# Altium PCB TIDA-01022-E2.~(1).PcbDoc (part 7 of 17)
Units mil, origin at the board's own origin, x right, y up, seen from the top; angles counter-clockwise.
Board outline 6929.13 x 11614.17 mil, 12 copper layers (L1_Top Layer, L2_GND, L3_GND, L4_Signal Layer 1, L5_GND, L6_PWR, L7_GND/PWR, L8_PWR, L9_GND/PWR, L10_Signal Layer 2, L11_GND, L12_Bottom Layer), stack 64.6 mil thick; 1711 components, 1001 nets, 5985 pads, 3200 vias.
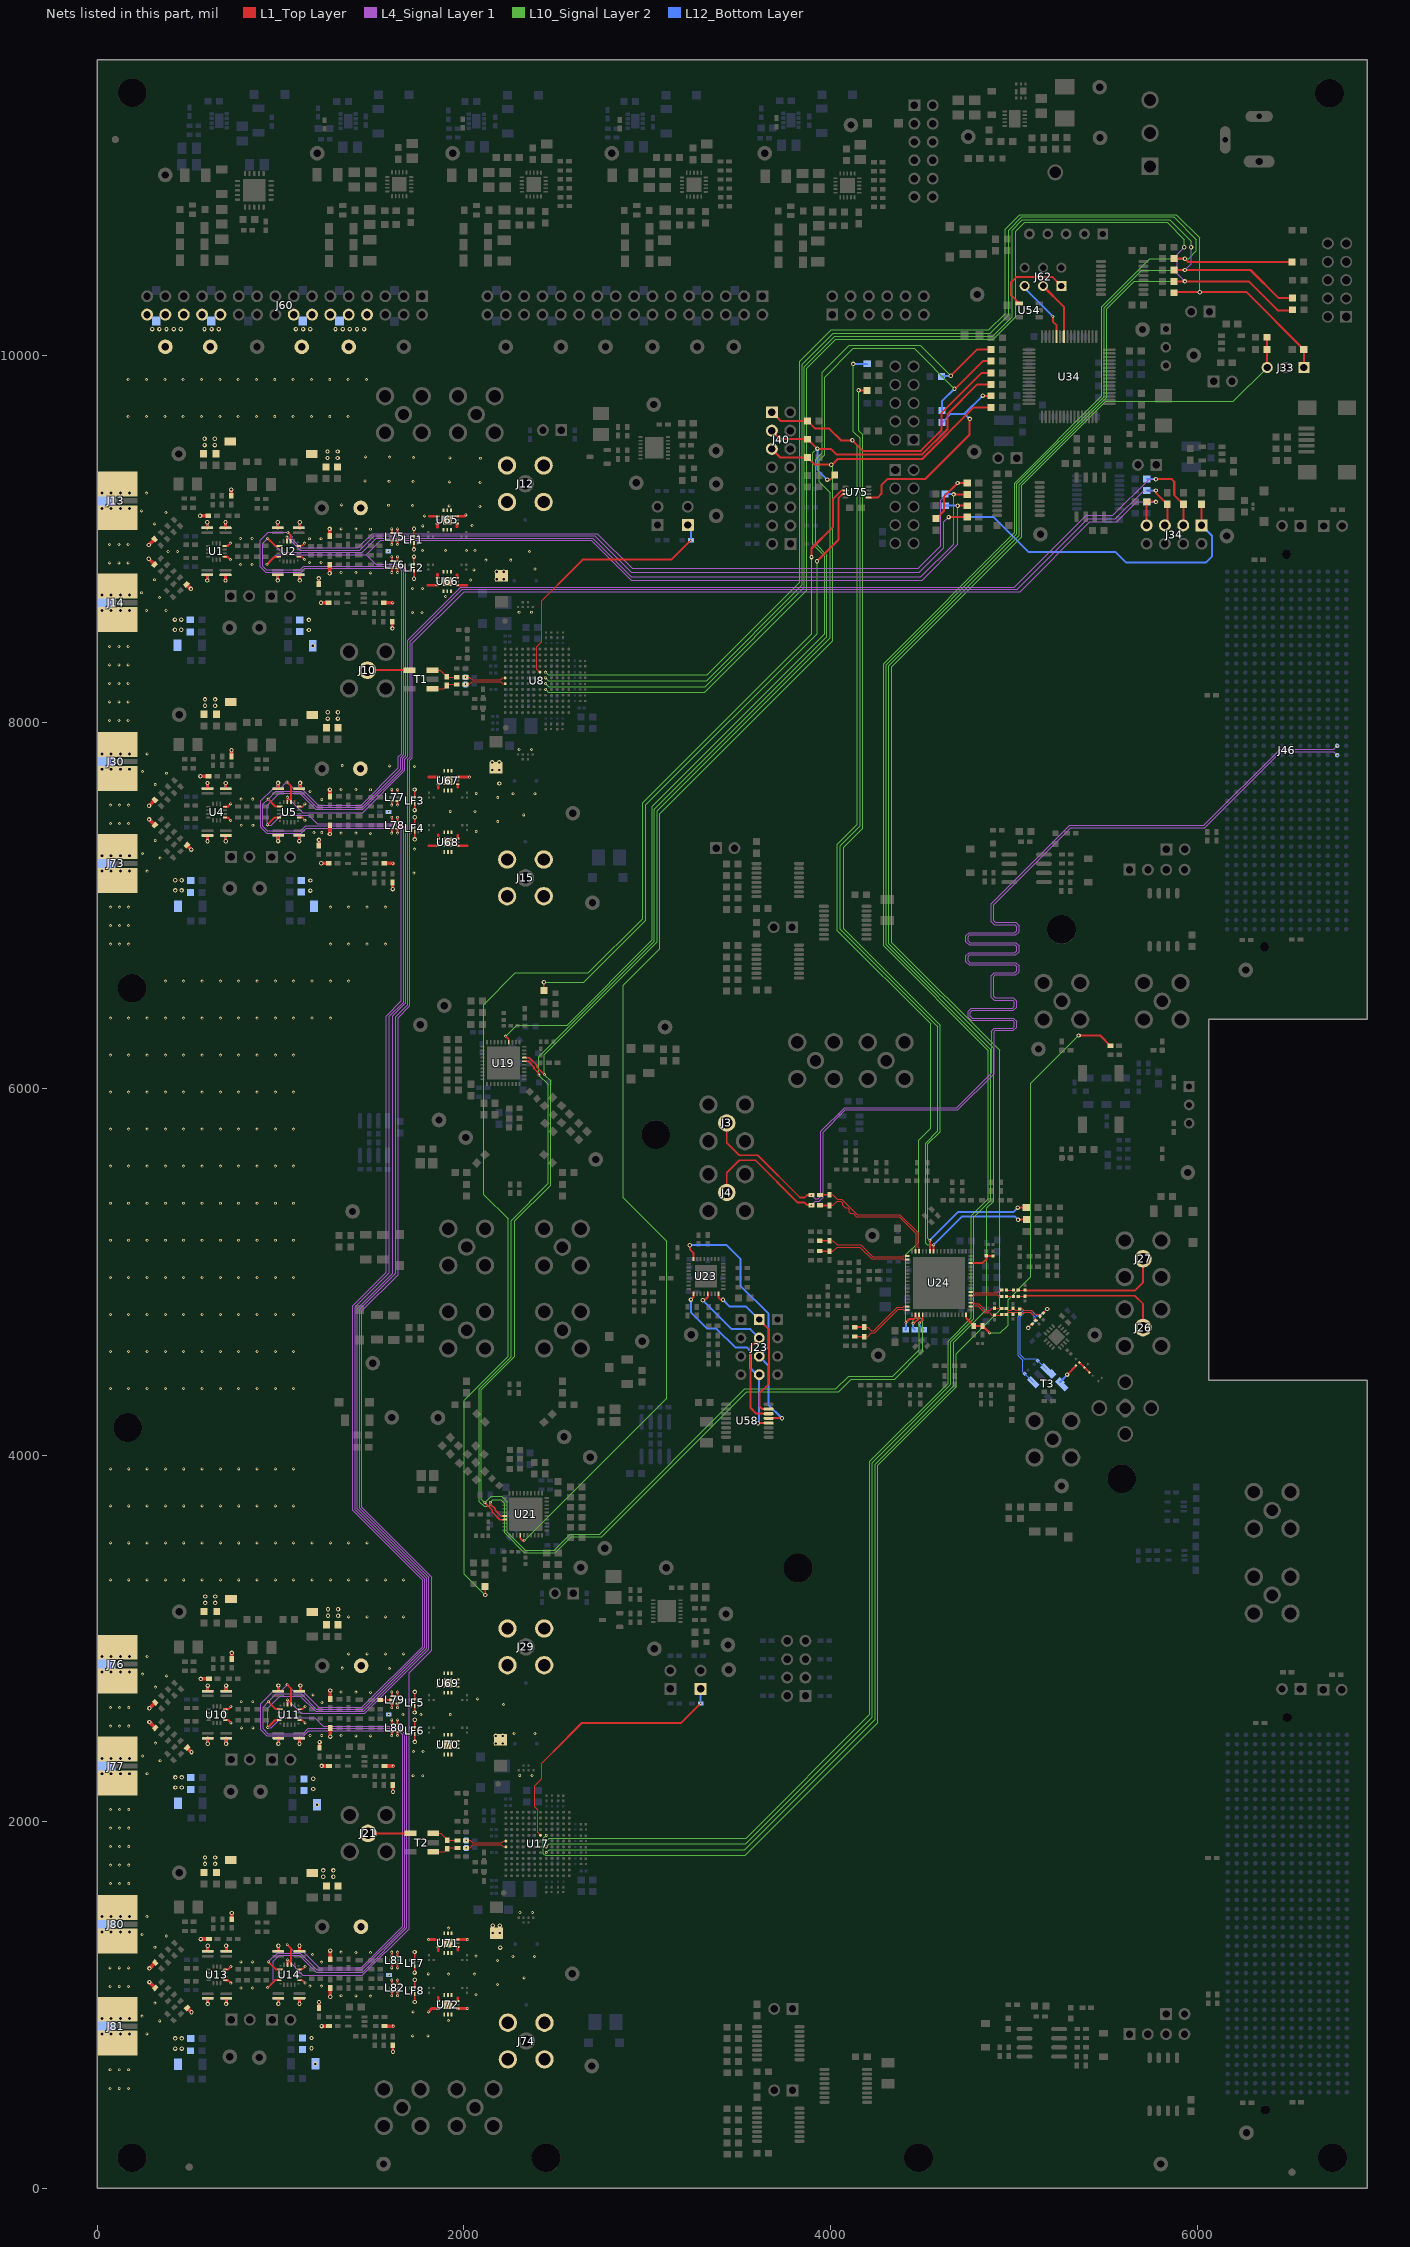
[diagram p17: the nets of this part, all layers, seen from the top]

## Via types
v1: diameter 16, hole 8, L1_Top Layer to L12_Bottom Layer, tented both sides, 1699 vias
v2: diameter 24, hole 12, L1_Top Layer to L12_Bottom Layer, tented both sides, 1501 vias

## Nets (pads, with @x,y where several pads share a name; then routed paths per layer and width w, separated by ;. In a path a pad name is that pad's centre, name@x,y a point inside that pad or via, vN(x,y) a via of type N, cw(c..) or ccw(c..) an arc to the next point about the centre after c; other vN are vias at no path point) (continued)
AGND: C1.2 C2.1 C3.1 C4.1 C5.1 C6.2 C7.2 C8.2 C9.2 C10.2 C12.2 C15.2 C17.2 C18.2 C19.2 C20.2 C21.1 C22.1 C23.1 C24.1 C25.1 C27.2 C28.2 C35.2 C36.1 C37.1 C38.1 C39.1 C40.2 C41.2 C42.2 C43.2 C44.2 C46.2 C49.2 C51.2 C52.2 C53.2 C54.2 C55.1 C56.1 C57.1 C58.1 C59.1 C61.2 C62.2 C161.2 C162.1 C163.1 C164.1 C165.1 C166.2 C167.2 C168.2 C169.2 C170.2 C172.2 C175.2 C177.2 C178.2 C179.2 C180.2 C181.1 C182.1 C183.1 C184.1 C185.1 C187.2 C188.2 C195.2 C196.1 C197.1 C198.1 C199.1 C200.2 C201.2 C202.2 C203.2 C204.2 C206.2 C209.2 C211.2 C212.2 C213.2 C214.2 C215.1 C216.1 C217.1 C218.1 C219.1 C221.2 C222.2 C637.2 C638.2 C639.1 C640.2 C641.1 C642.2 C648.2 C649.1 C650.2 C651.1 C652.2 C653.2 C658.2 C659.2 C663.1 C664.2 C665.1 C666.2 C670.2 C671.2 C672.1 C673.2 C674.1 C675.2 C688.2 C689.2 C691.1 C692.2 C693.1 C694.2 C699.2 C700.2 C701.1 C702.2 C703.1 C704.2 C708.2 C709.2 C710.1 C711.2 C712.1 C713.2 C717.2 C718.2 C719.1 C720.2 C721.1 C722.2 J12.2 J12.3 J12.4 J12.5 J13. J13.2 J13.3 J13.4 J14. J14.2 J14.3 J14.4 J15.2 J15.3 J15.4 J15.5 J29.2 J29.3 J29.4 J29.5 J30. J30.2 J30.3 J30.4 J60.8 J60.10 J60.12 J60.14 J60.16 J60.24 J60.26 J60.28 J60.30 J60.32 J73. J73.2 J73.3 J73.4 J74.2 J74.3 J74.4 J74.5 J76. J76.2 J76.3 J76.4 J77. J77.2 J77.3 J77.4 J80. J80.2 J80.3 J80.4 J81. J81.2 J81.3 J81.4 L68.2 L69.2 L70.2 L71.2 L75.1 L75.3 L75.4 L75.6 L76.1 L76.3 L76.4 L76.6 L77.1 L77.3 L77.4 L77.6 L78.1 L78.3 L78.4 L78.6 L79.1 L79.2 L79.3 L79.4 L79.6 L80.1 L80.3 L80.4 L80.6 L81.1 L81.3 L81.4 L81.6 L82.1 L82.3 L82.4 L82.6 L93.1 L94.1 L95.1 L96.1 LF1.2 LF1.5 LF2.2 LF2.5 LF3.2 LF3.5 LF4.2 LF4.5 LF5.2 LF5.5 LF6.2 LF6.5 LF7.2 LF7.5 LF8.2 LF8.5 R20.1 R21.1 R44.1 R45.1 R85.2 R101.1 R102.1 R125.1 R126.1 R483.1 R555.1 R558.1 R559.1 R564.1 R567.1 R568.1 R573.1 R576.1 R577.1 R582.1 R585.1 R642.1 TP15.1 TP28.1 TP29.1 TP50.1 TP51.1 TP52.1 TP53.1 TP64.1 U1.11 U1.14 U2.9 U2.12 U4.11 U4.14 U5.9 U5.12 U10.11 U10.14 U11.9 U11.12 U13.11 U13.14 U14.9 U14.12 U65.1 U65.3 U65.4 U65.5 U65.6 U65.7 U65.9 U65.10 U65.11 U65.12 U65.13 U66.1 U66.3 U66.4 U66.5 U66.6 U66.7 U66.9 U66.10 U66.11 U66.12 U66.13 U67.1 U67.3 U67.4 U67.5 U67.6 U67.7 U67.9 U67.10 U67.11 U67.12 U67.13 U68.1 U68.3 U68.4 U68.5 U68.6 U68.7 U68.9 U68.10 U68.11 U68.12 U68.13 U69.1 U69.3 U69.4 U69.5 U69.6 U69.7 U69.9 U69.10 U69.11 U69.12 U69.13 U70.1 U70.3 U70.4 U70.5 U70.6 U70.7 U70.9 U70.10 U70.11 U70.12 U70.13 U71.1 U71.3 U71.4 U71.5 U71.6 U71.7 U71.9 U71.10 U71.11 U71.12 U71.13 U72.1 U72.3 U72.4 U72.5 U72.6 U72.7 U72.9 U72.10 U72.11 U72.12 U72.13 | length 6689.4
  L1_Top Layer w8: U2.9@1099.21,8901.73 1114.81,8901.73 v1(1130.22,8886.32) ; U2.12@1099.21,8960.79 1114.81,8960.79 v1(1130.22,8976.2) ; U5.9@1101.01,7479.6 1116.6,7479.6 v1(1132.02,7464.19) ; U5.12@1101.01,7538.66 1116.6,7538.66 v1(1132.02,7554.07) ; U11.9@1102.53,2555.37 1118.12,2555.37 v1(1133.53,2539.96) ; U11.12@1102.53,2614.42 1118.12,2614.42 v1(1133.53,2629.84) ; U14.9@1102.6,1136.03 1118.2,1136.03 v1(1133.61,1120.62) ; U14.12@1102.6,1195.09 1118.2,1195.09 v1(1133.61,1210.5) ; v2(1727.01,8941.88) 1727.01,8977.01 LF1.5@1727.22,8977.22 ; LF1.2@1727.13,9010.68 v2(1727.13,9054.33) ; LF2.2@1727.22,8859 v2(1727.22,8902.65) ; v2(1727.41,8781.89) LF2.5@1727.41,8825.54 ; v2(1730.63,1177.1) 1730.63,1212.23 LF7.5@1730.84,1212.44 ; v2(1730.63,2596.2) 1730.63,2631.33 LF5.5@1730.84,2631.54 ; v2(1730.63,7519.8) 1730.63,7554.93 LF3.5@1730.84,7555.14 ; LF7.2@1730.74,1245.9 v2(1730.74,1289.55) ; LF3.2@1730.74,7588.6 v2(1730.74,7632.25) ; LF8.2@1730.84,1093.9 v2(1730.84,1137.87) ; LF6.2@1730.84,2513 v2(1730.84,2556.97) ; LF5.2@1730.84,2665 v2(1730.84,2708.65) ; LF4.2@1730.84,7436.6 v2(1730.84,7480.57) ; v2(1731.03,1017.11) LF8.5@1731.03,1060.75 ; v2(1731.03,7359.81) LF4.5@1731.03,7403.45 ; v2(1731.12,2436.21) LF6.5@1731.12,2479.85
  L1_Top Layer w10: v1(1606,7546.6) L77.3@1606,7569.91 ; v1(1637.5,7546.6) L77.4@1637.5,7569.91
  L1_Top Layer w11: R85.2@1542.66,2664.77 cw(c1543.97,2663.46) 1543.97,2665.31 R642.1@1598.13,2665.31 ; v1(1606,1050.9) L82.3@1606,1074.21 ; L82.1@1606,1113.59 v1(1606,1136.9) ; v1(1606,1202.9) L81.3@1606,1226.22 ; L81.1@1606,1265.59 v1(1606,1288.9) ; v1(1606,2470.31) L80.3@1606,2493.31 L80.3@1606,2493.63 ; L80.1@1606,2533 v1(1606,2556.31) ; v1(1606,2622.31) L79.3@1606,2645.63 ; L79.1@1606,2685 v1(1606,2708.31) ; v1(1606,7394.6) L78.3@1606,7417.71 L78.3@1606,7417.91 ; L78.1@1606,7457.28 v1(1606,7480.6) ; L77.1@1606,7609.28 v1(1606,7632.6) ; v1(1606,8816) L76.3@1606,8839.31 ; L76.1@1606,8878.69 v1(1606,8902) ; v1(1606,8968) L75.3@1606,8991.31 ; L75.1@1606,9030.69 v1(1606,9054) ; v1(1637.5,1050.9) L82.4@1637.5,1074.21 ; L82.6@1637.5,1113.59 v1(1637.5,1136.9) ; v1(1637.5,1202.9) L81.4@1637.5,1226.22 ; L81.6@1637.5,1265.59 v1(1637.5,1288.9) ; v1(1637.5,2470.31) L80.4@1637.5,2493.31 L80.4@1637.5,2493.63 ; L80.6@1637.5,2533 v1(1637.5,2556.31) ; v1(1637.5,2622.31) L79.4@1637.5,2645.63 ; L79.6@1637.5,2685 v1(1637.5,2708.31) ; v1(1637.5,7394.6) L78.4@1637.5,7417.71 L78.4@1637.5,7417.91 ; L78.6@1637.5,7457.28 v1(1637.5,7480.6) ; L77.6@1637.5,7609.28 v1(1637.5,7632.6) ; v1(1637.5,8816) L76.4@1637.5,8839.31 ; L76.6@1637.5,8878.69 v1(1637.5,8902) ; v1(1637.5,8968) L75.4@1637.5,8991.31 ; L75.6@1637.5,9030.69 v1(1637.5,9054)
  L1_Top Layer w12: U1.11@694.19,8901.46 709.78,8901.46 v1(725.19,8886.05) ; U1.14@694.19,8960.52 709.78,8960.52 v1(725.19,8975.93) ; U4.11@695.98,7479.34 711.58,7479.34 v1(726.99,7463.92) ; U4.14@695.98,7538.39 711.58,7538.39 v1(726.99,7553.8) ; U10.11@697.5,2555.1 713.1,2555.1 v1(728.51,2539.69) ; U10.14@697.5,2614.16 713.1,2614.16 v1(728.51,2629.57) ; U13.11@697.58,1135.76 713.17,1135.76 v1(728.59,1120.35) ; U13.14@697.58,1194.82 713.17,1194.82 v1(728.59,1210.23)
  L1_Top Layer w15: v2(598.91,8772.33) C21.1@598.91,8803.19 ; C2.1@598.91,9058.79 v2(598.91,9089.65) ; v2(600.71,7350.21) C55.1@600.71,7381.07 ; C36.1@600.71,7636.66 v2(600.71,7667.52) ; v2(602.23,2425.97) C181.1@602.23,2456.83 ; C162.1@602.23,2712.42 v2(602.23,2743.29) ; v2(602.3,1006.64) C215.1@602.3,1037.5 ; C196.1@602.3,1293.09 v2(602.3,1323.95) ; v2(698.91,8772.33) C22.1@698.91,8803.19 ; C3.1@698.91,9058.79 v2(698.91,9089.65) ; v2(700.71,7350.21) C56.1@700.71,7381.07 ; C37.1@700.71,7636.66 v2(700.71,7667.52) ; v2(702.23,2425.97) C182.1@702.23,2456.83 ; C163.1@702.23,2712.42 v2(702.23,2743.29) ; v2(702.3,1006.64) C216.1@702.3,1037.5 ; C197.1@702.3,1293.09 v2(702.3,1323.95) ; v2(984.09,8772.6) C23.1@984.09,8803.46 ; C4.1@984.09,9059.05 v2(984.09,9089.92) ; v2(985.89,7350.47) C57.1@985.89,7381.34 ; C38.1@985.89,7636.93 v2(985.89,7667.79) ; v2(987.41,2426.24) C183.1@987.41,2457.1 ; C164.1@987.41,2712.69 v2(987.41,2743.55) ; v2(987.48,1006.9) C217.1@987.48,1037.77 ; C198.1@987.48,1293.36 v2(987.48,1324.22) ; v2(1100.89,7350.47) C58.1@1100.89,7381.34 ; v2(1102.41,2426.24) C184.1@1102.41,2457.1 ; v2(1102.48,1006.9) C218.1@1102.48,1037.76 ; C199.1@1102.48,1293.36 v2(1102.48,1324.22) ; v2(1104.09,8772.6) C24.1@1104.09,8803.46 ; C5.1@1104.09,9059.05 v2(1104.09,9089.92) ; C39.1@1105.89,7636.93 v2(1105.89,7667.79) ; C165.1@1107.41,2712.69 v2(1107.41,2743.55) ; C27.2@1207.68,8752.9 v2(1207.68,8783.76) ; C61.2@1208.47,7326.37 v2(1208.47,7357.24) ; C221.2@1209.11,984.88 v2(1209.11,1015.74) ; C187.2@1212.04,2404.21 v2(1212.04,2435.08) ; R558.1@1607.91,8547.16 1607.91,8512.21 v2(1609.19,8510.93) ; R567.1@1609.71,7125.04 1609.71,7090.09 v2(1610.99,7088.8) ; R576.1@1611.23,2200.8 1611.23,2165.85 v2(1612.51,2164.57) ; R585.1@1611.3,781.47 1611.3,746.52 v2(1612.59,745.23) ; 1803.55,8746.76 U66.3@1855.38,8746.76 ; v1(1805.24,963.3) 1823.92,981.98 U72.3@1859,981.98 ; v1(1807.16,1357.84) U71.1@1859,1357.84 ; 1807.16,7324.68 U68.3@1859,7324.68 ; 1807.16,7700.54 U67.1@1859,7700.54 ; 1810,9122.62 U65.1@1855.38,9122.62 ; U66.1@1855.38,8786.92 1855.38,8806.6 ; 1855.38,9062.78 U65.3@1855.38,9082.46 ; U72.1@1859,1022.14 1859,1041.81 ; 1859,1298 U71.3@1859,1317.68 ; U68.1@1859,7364.84 1859,7384.52 ; 1859,7640.7 U67.3@1859,7660.38 ; U66.7@1962.46,8746.76 2014.3,8746.76 ; U66.9@1962.46,8786.92 1962.46,8803.52 ; 1962.46,9065.86 U65.7@1962.46,9082.46 ; U65.9@1962.46,9122.62 2002.62,9122.62 v1(2010,9130) ; U72.7@1966.08,981.98 v1(2017.91,981.98) ; U72.9@1966.08,1022.14 1966.08,1038.74 ; 1966.08,1301.08 U71.7@1966.08,1317.68 ; U71.9@1966.08,1357.84 v1(2017.91,1357.84) ; U68.7@1966.08,7324.68 2017.91,7324.68 ; U68.9@1966.08,7364.84 1966.08,7381.44 ; 1966.08,7643.78 U67.7@1966.08,7660.38 ; U67.9@1966.08,7700.54 1966.62,7700 v1(2030,7700)
  L1_Top Layer w20: v2(280.45,8891.05) R21.1@312.21,8859.29 ; v2(280.45,8965.93) R20.1@312.21,8997.69 ; v2(282.24,7468.92) R45.1@314.01,7437.16 ; v2(282.24,7543.8) R44.1@314.01,7575.57 ; v2(283.76,2544.69) R102.1@315.52,2512.93 ; v2(283.76,2619.57) R101.1@315.52,2651.33 ; v2(283.84,1125.35) R126.1@315.6,1093.59 ; v2(283.84,1200.23) R125.1@315.6,1232 ; R555.1@485.91,8750.79 v2(510.19,8726.5) ; R564.1@487.71,7328.66 v2(511.99,7304.37) ; R573.1@489.23,2404.42 v2(513.51,2380.14) ; R582.1@489.3,985.09 v2(513.59,960.8) ; v2(560.31,9125.93) 560.25,9125.99 C1.2@604.79,9125.99 ; v2(562.11,7703.8) 562.05,7703.86 C35.2@606.59,7703.86 ; v2(563.63,2779.57) 563.57,2779.63 C161.2@608.11,2779.63 ; v2(563.7,1360.23) 563.65,1360.29 C195.2@608.18,1360.29 ; R483.1@729.91,9234.41 v2(729.91,9268.12) ; R559.1@731.71,7812.28 v2(731.71,7846) ; R568.1@733.23,2888.05 v2(733.23,2921.76) ; R577.1@733.3,1468.71 v2(733.3,1502.43) ; v2(1219.87,8651.26) C25.1@1260.47,8651.26 ; v2(1221.67,7229.13) C59.1@1262.27,7229.13 ; v2(1223.18,2304.9) C185.1@1263.79,2304.9 ; v2(1223.26,885.56) C219.1@1263.86,885.56 ; C15.2@1266.72,8858.51 1266.87,8858.36 v2(1266.87,8811.43) ; C10.2@1266.72,9015.76 v2(1266.72,9053.6) ; C44.2@1268.52,7593.63 v2(1268.52,7631.48) ; v2(1268.67,7389.3) C49.2@1268.67,7436.24 ; C170.2@1269.89,2669.54 v2(1269.89,2716.48) ; C204.2@1269.96,1250.21 v2(1269.96,1297.14) ; C175.2@1270.04,2512.15 1270.19,2512 v2(1270.19,2465.07) ; v2(1270.26,1045.73) C209.2@1270.26,1092.67 ; C28.2@1562.71,8651.26 1610.52,8651.26 v1(1610.52,8650.6) ; C62.2@1564.51,7229.13 1612.32,7229.13 v1(1612.32,7228.48) ; C188.2@1566.03,2304.9 1613.84,2304.9 v1(1613.84,2304.24) ; C222.2@1566.11,885.56 v1@1613.91,885.56
  L12_Bottom Layer w15: v2(598.91,8772.33) C17.2@598.91,8803.19 ; C6.2@598.91,9058.79 v2(598.91,9089.65) ; v2(600.71,7350.21) C51.2@600.71,7381.07 ; C40.2@600.71,7636.66 v2(600.71,7667.52) ; v2(602.23,2425.97) C177.2@602.23,2456.83 ; C166.2@602.23,2712.42 v2(602.23,2743.29) ; v2(602.3,1006.64) C211.2@602.3,1037.5 ; C200.2@602.3,1293.09 v2(602.3,1323.95) ; v2(698.91,8772.33) C18.2@698.91,8803.19 ; C7.2@698.91,9058.79 v2(698.91,9089.65) ; v2(700.71,7350.21) C52.2@700.71,7381.07 ; C41.2@700.71,7636.66 v2(700.71,7667.52) ; v2(702.23,2425.97) C178.2@702.23,2456.83 ; C167.2@702.23,2712.42 v2(702.23,2743.29) ; v2(702.3,1006.64) C212.2@702.3,1037.5 ; C201.2@702.3,1293.09 v2(702.3,1323.95) ; v2(984.09,8772.6) C19.2@984.09,8803.46 ; C8.2@984.09,9059.05 v2(984.09,9089.92) ; v2(985.89,7350.47) C53.2@985.89,7381.34 ; C42.2@985.89,7636.93 v2(985.89,7667.79) ; v2(987.41,2426.24) C179.2@987.41,2457.1 ; C168.2@987.41,2712.69 v2(987.41,2743.55) ; v2(987.48,1006.9) C213.2@987.48,1037.77 ; C202.2@987.48,1293.36 v2(987.48,1324.22) ; v2(1100.89,7350.47) C54.2@1100.89,7381.34 ; v2(1102.41,2426.24) C180.2@1102.41,2457.1 ; v2(1102.48,1006.9) C214.2@1102.48,1037.77 ; C203.2@1102.48,1293.36 v2(1102.48,1324.22) ; v2(1104.09,8772.6) C20.2@1104.09,8803.46 ; C9.2@1104.09,9059.05 v2(1104.09,9089.92) ; C43.2@1105.89,7636.93 v2(1105.89,7667.79) ; C169.2@1107.41,2712.69 v2(1107.41,2743.55)
  other v1: 69.24,546.21 119.24,546.21 169.24,546.21 69.24,647.21 119.24,647.21 169.24,647.21 1720.14,832.11 1803.14,832.11 269.51,843 1613.91,884.91 340.23,913.71 1915,915 243.4,939.82 1722.24,963.3 1912.54,1002.06 314.11,1010.53 1490.13,1048.9 1410,1049.9 1329.87,1050.9 2065.45,1058.43 783.24,1093.3 846.24,1093.3 69.24,1102.3 119.24,1102.3 169.24,1102.3 1159.24,1103.3 1222.24,1103.3 2182.45,1113.43 2328,1148 1591.36,1163.94 1805,1170 1915,1169.43 2058.45,1169.43 69.24,1203.3 119.24,1203.3 169.24,1203.3 1222.24,1234.3 782.77,1235.7 845.77,1235.7 2182.45,1244.43 2266.45,1265.43 2385.45,1265.43 2065.45,1267.43 1174,1276 1489.98,1286.9 1409.85,1287.9 1329.72,1288.9 314.11,1315.55 1912.54,1337.76 375.58,1377.02 243.4,1386.27 1915,1420 269.51,1483.09 2305.26,1505.23 2372.85,1505.23 71.08,1662.55 121.08,1662.55 171.08,1662.55 71.08,1763.55 121.08,1763.55 171.08,1763.55 71.08,1864.55 121.08,1864.55 171.08,1864.55 71.08,1965.55 121.08,1965.55 171.08,1965.55 71.08,2066.55 121.08,2066.55 171.08,2066.55 1721.98,2251.45 1774.98,2251.45 2304.05,2253.38 2371.64,2253.38 271.36,2262.33 342.07,2333.04 245.24,2359.15 1724.08,2382.64 1777.08,2382.64 315.95,2429.86 1490.13,2468.31 1410,2469.31 1161,2471 1224,2471 1329.87,2470.31 2273,2482 2387,2482 785.08,2512.64 848.08,2512.64 71.08,2521.64 121.08,2521.64 171.08,2521.64 1667,2585 1765,2585 1925,2585 1589.76,2585.46 71.08,2622.64 121.08,2622.64 171.08,2622.64 2216,2639 1225.04,2651.97 784.61,2655.03 847.61,2655.03 2074,2671 1177,2693 1489.98,2706.31 1409.85,2707.31 1329.72,2708.31 315.95,2734.89 1912.54,2756.86 377.42,2796.36 245.24,2805.6 1593.09,2836.33 1335.9,2838.43 271.36,2902.42 1371,2916 1471,2916 1571,2916 1671,2916 1371,3118 1471,3118 1571,3118 1671,3118 71,3320 171,3320 271,3320 371,3320 471,3320 571,3320 671,3320 771,3320 871,3320 971,3320 1071,3320 1171,3320 1271,3320 1371,3320 1471,3320 1571,3320 1671,3320 71,3522 171,3522 271,3522 371,3522 471,3522 571,3522 671,3522 771,3522 871,3522 971,3522 1071,3522 1171,3522 1271,3522 1371,3522 1471,3522 71,3724 171,3724 271,3724 371,3724 471,3724 571,3724 671,3724 771,3724 871,3724 971,3724 1071,3724 71,3926 171,3926 271,3926 371,3926 471,3926 571,3926 671,3926 771,3926 871,3926 971,3926 1071,3926 70.8,4364.78 170.8,4364.78 270.8,4364.78 370.8,4364.78 470.8,4364.78 570.8,4364.78 670.8,4364.78 770.8,4364.78 870.8,4364.78 970.8,4364.78 1070.8,4364.78 70.8,4566.78 170.8,4566.78 270.8,4566.78 370.8,4566.78 470.8,4566.78 570.8,4566.78 670.8,4566.78 770.8,4566.78 870.8,4566.78 970.8,4566.78 1070.8,4566.78 70.8,4768.78 170.8,4768.78 270.8,4768.78 370.8,4768.78 470.8,4768.78 570.8,4768.78 670.8,4768.78 770.8,4768.78 870.8,4768.78 970.8,4768.78 1070.8,4768.78 70.8,4970.78 170.8,4970.78 270.8,4970.78 370.8,4970.78 470.8,4970.78 570.8,4970.78 670.8,4970.78 770.8,4970.78 870.8,4970.78 970.8,4970.78 1070.8,4970.78 70.8,5172.78 170.8,5172.78 270.8,5172.78 370.8,5172.78 470.8,5172.78 570.8,5172.78 670.8,5172.78 770.8,5172.78 870.8,5172.78 970.8,5172.78 1070.8,5172.78 70.8,5374.78 170.8,5374.78 270.8,5374.78 370.8,5374.78 470.8,5374.78 570.8,5374.78 670.8,5374.78 770.8,5374.78 870.8,5374.78 970.8,5374.78 1070.8,5374.78 70.8,5576.78 170.8,5576.78 270.8,5576.78 370.8,5576.78 470.8,5576.78 570.8,5576.78 670.8,5576.78 770.8,5576.78 870.8,5576.78 970.8,5576.78 1070.8,5576.78 70.8,5778.78 170.8,5778.78 270.8,5778.78 370.8,5778.78 470.8,5778.78 570.8,5778.78 670.8,5778.78 770.8,5778.78 870.8,5778.78 970.8,5778.78 1070.8,5778.78 70.8,5980.78 170.8,5980.78 270.8,5980.78 370.8,5980.78 470.8,5980.78 570.8,5980.78 670.8,5980.78 770.8,5980.78 870.8,5980.78 970.8,5980.78 1070.8,5980.78 70.8,6182.78 170.8,6182.78 270.8,6182.78 370.8,6182.78 470.8,6182.78 570.8,6182.78 670.8,6182.78 770.8,6182.78 870.8,6182.78 970.8,6182.78 1070.8,6182.78 70.8,6384.78 170.8,6384.78 270.8,6384.78 370.8,6384.78 470.8,6384.78 570.8,6384.78 670.8,6384.78 770.8,6384.78 870.8,6384.78 970.8,6384.78 1070.8,6384.78 1170.8,6384.78 1270.8,6384.78 370.8,6586.78 470.8,6586.78 570.8,6586.78 670.8,6586.78 770.8,6586.78 870.8,6586.78 970.8,6586.78 1070.8,6586.78 1170.8,6586.78 1270.8,6586.78 1370.8,6586.78 70.8,6788.78 120.8,6788.78 170.8,6788.78 1270.8,6788.78 1370.8,6788.78 1470.8,6788.78 1570.8,6788.78 70.8,6889.78 120.8,6889.78 170.8,6889.78 70.8,6990.78 120.8,6990.78 170.8,6990.78 1270.8,6990.78 1370.8,6990.78 1470.8,6990.78 1570.8,6990.78 1727,7176 271.07,7186.57 341.78,7257.28 244.96,7283.39 1729.1,7307.19 1925,7344.31 315.67,7354.1 1490.13,7392.6 1410,7393.6 1329.87,7394.6 1181,7397 1224,7397 2067,7402 784.8,7436.87 847.8,7436.87 70.8,7445.87 120.8,7445.87 170.8,7445.87 2184,7457 2326,7494 1588.24,7509.7 1925,7513 2060,7513 70.8,7546.87 120.8,7546.87 170.8,7546.87 1223.8,7577.87 784.33,7579.27 847.33,7579.27 2184,7588 2268,7609 2387,7609 2067,7611 1161,7622 1489.98,7630.6 1409.85,7631.6 1329.72,7632.6 315.67,7659.13 1925,7680 377.14,7720.59 244.96,7729.84 1731,7758 1592.81,7760.57 1335.62,7762.66 271.07,7826.66 2301.08,7851.2 2368.67,7851.2 67,8008.91 117,8008.91 167,8008.91 67,8109.91 117,8109.91 167,8109.91 67,8210.91 117,8210.91 167,8210.91 67,8311.91 117,8311.91 167,8311.91 67,8412.91 117,8412.91 167,8412.91 1717.9,8597.81 1770.9,8597.81 2301,8599 2368.59,8599 267.27,8608.69 375.27,8608.69 337.98,8679.4 1900,8685 241.16,8705.52 1720,8729 1773,8729 1908.92,8766.84 2035,8775 311.87,8776.23 1490.13,8814 1410,8815 1329.87,8816 2054,8830 2387,8835 781,8859 844,8859 67,8868 117,8868 167,8868 1157,8871 1220,8871 2119,8884 2255,8884 2358,8930 385.87,8930.43 435.87,8930.43 1586.45,8931.82 1773,8935 1898,8935 2013,8935 2060,8935 67,8969 117,8969 167,8969 1157,9000 1220,9000 780.53,9001.4 843.53,9001.4 1489.98,9052 1409.85,9053 1329.72,9054 1775,9070 2044,9072 311.87,9081.25 1908.92,9102.54 1785,9125 373.34,9142.72 241.16,9151.96 2086.19,9176.9 1919.19,9178.9 1720.2,9180.6 1589.01,9182.69 1331.82,9184.79 267.27,9248.79 2088.29,9308.09 1921.29,9310.09 1722.3,9311.78 1591.11,9313.88 1459.92,9315.98 2090.39,9439.28 1923.39,9441.28 1724.4,9442.97 1593.21,9445.07 1462.02,9447.17 167.68,9666.36 267.68,9666.36 367.68,9666.36 467.68,9666.36 567.68,9666.36 667.68,9666.36 767.68,9666.36 867.68,9666.36 967.68,9666.36 1067.68,9666.36 1167.68,9666.36 1267.68,9666.36 1367.68,9666.36 167.68,9868.36 267.68,9868.36 367.68,9868.36 467.68,9868.36 567.68,9868.36 667.68,9868.36 767.68,9868.36 867.68,9868.36 967.68,9868.36 1067.68,9868.36 1167.68,9868.36 1267.68,9868.36 1367.68,9868.36 1467.68,9868.36
  other v2: 1188.95,679.38 424.74,762.94 459.74,762.94 1168.17,765.1 424.74,818.19 459.74,818.19 1168.17,820.35 2198,1314 2157.41,1392.9 2195.33,1393 2157.41,1433.9 2195.33,1434 1232.23,1700.1 1287.48,1700.1 1232.23,1735.1 1287.48,1735.1 586.91,1770.17 642.17,1770.17 586.91,1805.17 642.17,1805.17 1198.29,2093.46 1177.5,2179.18 425.66,2187.28 460.66,2187.28 1177.5,2234.43 425.66,2242.53 460.66,2242.53 2173.08,2427.9 2211,2428 2173.08,2468.9 2211,2469 1258.15,3124.43 1313.41,3124.43 1258.15,3159.43 1313.41,3159.43 587.84,3194.5 643.09,3194.5 587.84,3229.5 643.09,3229.5 1161.8,7080.27 424.56,7081.57 459.56,7081.57 1161.8,7135.53 424.56,7136.83 459.56,7136.83 2193,7665 2154.08,7738.9 2192,7739 2154.08,7779.9 2192,7780 1257.05,8018.73 1312.31,8018.73 1257.05,8053.73 1312.31,8053.73 586.74,8088.8 641.99,8088.8 586.74,8123.8 641.99,8123.8 1174.71,8416.35 1153.93,8502.07 422.77,8503.7 457.77,8503.7 1153.93,8557.32 422.77,8558.95 457.77,8558.95 2179.08,8778.9 2217,8779 2179.08,8819.9 2217,8820 1255.26,9440.86 1310.51,9440.86 1255.26,9475.86 1310.51,9475.86 584.94,9510.93 640.19,9510.93 584.94,9545.93 640.19,9545.93 299,10144 338,10144 377,10144 416,10144 455,10144 584,10144 623,10144 662,10144 1083,10144 1122,10144 1161,10144 1299,10144 1338,10144 1377,10144 1416,10144 1455,10144
BADC1_SCS: J33.1 R380.2 R400.2 U8.E8 | length 6877.2
  L1_Top Layer w11: R400.2@5873.84,10342.12 5876.72,10345 v2(6014,10345) 6269.5,10345 R380.2@6582,10032.5 J33.1@6582,9934
  L10_Signal Layer 2 w3.5: v1(2445.41,8272.34) 2460.16,8257.59 2597.38,8257.59
  L10_Signal Layer 2 w6.5: 2597.38,8257.59 3327.59,8257.59 3832.5,8762.5 3832.5,9967.5 4005,10140 4864,10140 4952,10228 4952,10688 5033,10769 5887,10769 6014,10642 v2(6014,10345)
BADC2_SCS: J33.3 R382.2 R416.2 U17.E8 | length 11567.2
  L1_Top Layer w11: R382.2@6380.5,10099 6381.5,10098 R416.2@6381.5,10033 6381.5,9934.5 J33.3@6382,9934
  L10_Signal Layer 2 w3.5: v1(2448.74,1926.34) 2433.33,1910.93 2433.33,1826.4 2442.63,1817.1 2601.3,1817.1
  L10_Signal Layer 2 w6.5: 2601.3,1817.1 3533.1,1817.1 4257,2541 4257,3946 4685,4374 4685,4553.68 4922.5,4791.18 4922.5,6208.7 4334,6797.2 4334,8300.8 5044,9010.8 5044,9291 5502,9749 6197,9749 J33.3@6382,9934
BADC_SCK: R375.1 R394.2 U8.F8 U17.F8 | length 17716.6
  L1_Top Layer w11: R394.2@5873.84,10528.12 v2(5933,10528.12) 5951.07,10510.05 R375.1@6516.79,10510.05
  L10_Signal Layer 2 w3.5: v1(2445.41,8240.84) 2460.16,8226.09 2597.97,8226.09 ; v1(2448.74,1894.85) 2465.49,1911.59 2601.3,1911.59
  L10_Signal Layer 2 w6.5: 2597.97,8226.09 3323.09,8226.09 3845,8748 3845,9952 4014,10121 4870,10121 4971,10222 4971,10684 5043,10756 5872,10756 5996,10632 5996,10570 5954.12,10528.12 v2(5933,10528.12) 5740.11,10528.12 5479,10267.01 5479,9779.03 5004,9304.03 5004,9034.44 4289,8319.44 4289,6778.56 4860,6207.56 4860,5398.01 4768.72,5306.73 4768.72,4748.72 4642,4622 4642,4394 4214,3966 4214,2585.66 3539.94,1911.59 2601.3,1911.59
BADC_SDI: R377.1 R396.2 U8.G8 U17.G8 | length 17780
  L1_Top Layer w11: R396.2@5873.84,10466.12 v2(5933,10466.12) 6290.88,10466.12 6443.95,10313.05 R377.1@6519.79,10313.05
  L4_Signal Layer 1 w5.5: v2(5933,10466.12) 5967,10500.12 v2(5967,10590)
  L10_Signal Layer 2 w3.5: v1(2445.41,8209.35) 2461.58,8193.17 2597.97,8193.17 ; v1(2448.74,1863.35) 2465.49,1880.1 2601.3,1880.1
  L10_Signal Layer 2 w6.5: 2597.97,8193.17 3316.17,8193.17 3857.5,8734.5 3857.5,9939.5 4023,10105 4884,10105 4991,10212 4991,10684 5047,10740 5851,10740 5967,10624 v2(5967,10590) ; 2601.3,1880.1 3538.1,1880.1 4228,2570 4228,3958 4656,4386 4656,4618.32 4781.22,4743.54 4781.22,5299.43 4874,5392.21 4874,6213.36 4303,6784.36 4303,8313.64 5016.5,9027.14 5016.5,9298.86 5493,9775.36 5493,10261.21 5697.9,10466.12 v2(5933,10466.12)
BADC_SDO: R379.1 R398.2 U8.H8 U17.H8 | length 17822.1
  L1_Top Layer w11: R398.2@5873.84,10404.12 v2(5933,10404.12) 6280.88,10404.12 6439.07,10245.93 R379.1@6519.79,10245.93
  L4_Signal Layer 1 w5.5: v2(5930,10590) 5892,10552 5892,10445.12 v2(5933,10404.12)
  L10_Signal Layer 2 w3.5: v1(2445.41,8177.85) 2460.16,8163.1 2483.02,8163.1 2483.09,8163.17 2502.22,8163.17 2502.29,8163.1 2546.01,8163.1 2546.08,8163.17 2597.97,8163.17 ; v1(2448.74,1831.85) 2464.06,1847.18 2601.3,1847.18
  L10_Signal Layer 2 w6.5: 2597.97,8163.17 3313.17,8163.17 3870,8720 3870,9931 4027.5,10088.5 4888.5,10088.5 5010,10210 5010,10678 5058,10726 5836,10726 5930,10632 v2(5930,10590) ; 2601.3,1847.18 3531.18,1847.18 4243,2559 4243,3952 4671,4380 4671,4615.64 4852,4796.64 4852,5349 4889,5386 4889,6219.57 4318,6790.57 4318,8307.43 5029,9018.43 5029,9293.68 5508,9772.68 5508,10255 5657.12,10404.12 v2(5933,10404.12)
BDBUS0: J62.3 U34.26 | length 323.5
  L1_Top Layer w11: J62.3@5159,10379 5272.36,10265.64 U34.26@5272.36,10102.47
BDBUS1: J62.1 U54.4 | length 440.2
  L1_Top Layer w11: U54.4@5029.75,10283.37 4985,10328.12 4985,10400 5012,10427 5211,10427 J62.1@5259,10379
BDBUS2: J62.5 U34.28 | length 348.6
  L1_Top Layer w11: v1(5212.88,10213.47) 5212.88,10184.46 5232.99,10164.35 U34.28@5232.99,10102.47
  L12_Bottom Layer w11: J62.5@5059,10379 5059,10367.36 v1(5212.88,10213.47)
BLMH1_SCS: J34.1 R381.2 R402.2 U2.15 | length 5954
  L1_Top Layer w11: U2.15@1034.25,8986.38 v1(1034.25,9009) ; v2(4644,9118) 4745.12,9118 R402.2@4745.32,9118.2 ; R381.2@6021.5,9186 R381.2@6024,9188.5 J34.1@6024,9073
  L4_Signal Layer 1 w5.5: v1@1033,9010 1106,8937 1431,8937 1510,9016 2714,9016 2913,8817 4484,8817 4618,8951 4618,9092 v2(4644,9118)
  L12_Bottom Layer w11: v2(4644,9118) 4890,9118 5079,8929 5553,8929 5612,8870 6047,8870 6082,8905 6082,9015 J34.1@6024,9073
BLMH2_SCS: J34.3 R383.2 R424.2 U5.15 | length 6372.2
  L1_Top Layer w11: U5.15@1036,7566.2 v1(1036,7590) ; v2(5775,9325.2) 5861.8,9325.2 5875,9312 5875,9238.5 R383.2@5925,9188.5 5925,9074 J34.3@5924,9073
  L4_Signal Layer 1 w5.5: v1(1036,7590) 1120,7506 1446.79,7506 1677,7736.21 1677,7796.53 1694.5,7814.03 1694.5,8446.5 1983,8735 5002,8735 5394,9127 5540,9127 5738.2,9325.2 v2(5775,9325.2)
  L12_Bottom Layer w11: R424.2@5725.31,9325.2 v2(5775,9325.2)
BLMH3_SCS: J34.5 R384.2 R423.2 U11.15 | length 11423.1
  L1_Top Layer w11: v1(1037.52,2665.77) 1037.52,2640.06 U11.15@1037.57,2640.01 ; v2(5775,9263.2) 5775,9250.5 R384.2@5837,9188.5 5837,9086 J34.5@5824,9073
  L4_Signal Layer 1 w5.5: v1(1037.52,2665.77) 1112.28,2591 1457.36,2591 1808.5,2942.14 1808.5,3333.29 1430,3711.79 1430,4795.74 1627,4992.74 1627,6391.26 1693.5,6457.76 1693.5,7163.93 1693.45,7163.98 1693.45,7187.39 1693.5,7187.44 1693.5,7796.76 1706,7809.26 1706,8440 1989.5,8723.5 5018.5,8723.5 5404,9109 5553,9109 5707.2,9263.2 v2(5775,9263.2)
  L12_Bottom Layer w11: R423.2@5725.31,9263.2 v2(5775,9263.2)
BLMH4_SCS: J34.7 R385.2 R421.2 U14.15 | length 12770.1
  L1_Top Layer w11: v1(1037.59,1246.43) 1037.59,1220.73 U14.15@1037.64,1220.68 ; J34.7@5724,9073 5724,9199.89 R385.2@5726.13,9202.01 5774.19,9202.01 v2(5775,9201.2)
  L4_Signal Layer 1 w5.5: v1(1037.59,1246.43) 1121.59,1162.43 1446.22,1162.43 1700,1416.21 1700,2814 1823,2937 1823,3335.05 1442,3716.05 1442,4787 1640,4985 1640,6388 1705,6453 1705,7168.69 1704.95,7168.75 1704.95,7182.62 1705,7182.67 1705,7792 1717.5,7804.5 1717.5,8429.24 2000.26,8712 5034,8712 5414,9092 5561,9092 5670.2,9201.2 v2(5775,9201.2)
  L12_Bottom Layer w11: R421.2@5725.31,9201.2 v2(5775,9201.2)
BLMH_CLK: R374.1 R409.2 U2.14 U5.14 U11.14 U14.14 | length 17517.5
  L1_Top Layer w11: v1(1034,7673) 1056.5,7650.5 1056.5,7565.02 U5.14@1055.73,7564.25 ; v1(1035.52,2748.77) 1057.25,2727.03 U11.14@1057.25,2640.01 ; v1(1035.59,1329.43) 1057.33,1307.7 U14.14@1057.33,1220.68 ; v1(1039,9035) 1053.93,9020.07 U2.14@1053.93,8986.38 ; R374.1@4576,9110 4620,9154 4620,9231.2 v2(4693,9304.2) R409.2@4745.32,9304.2
  L4_Signal Layer 1 w5.5: v1(1035.59,1329.43) 1069.59,1295.43 1117.59,1295.43 1209.59,1203.43 1438.43,1203.43 1665.5,1430.5 1665.5,2474.5 1644.23,2495.77 1152.77,2495.77 1126.5,2469.5 925.02,2469.5 892.02,2502.5 892.02,2645.27 959.52,2712.77 999.52,2712.77 v1(1035.52,2748.77) 1069.52,2714.77 1117.52,2714.77 1206.78,2625.5 1443.07,2625.5 1774,2956.43 1774,3319 1393,3700 1393,4815 1576,4998 1576,6396 1659,6479 1659,7149.64 1658.95,7149.69 1658.95,7201.68 1659,7201.73 1659,7409.24 1648.24,7420 1138.57,7420 1113.07,7394.5 922.74,7394.5 890.5,7426.74 890.5,7569.5 958,7637 998,7637 v1(1034,7673) 1068,7639 1112,7639 1204,7547 1439,7547 1642.5,7750.5 1642.5,7810.82 1660,7828.32 1660,8825 1647,8838 1130.26,8838 1110.76,8818.5 917.24,8818.5 889,8846.74 889,8993 931,9035 v1(1039,9035) 1062,9012 1062,8998 1109.5,8950.5 1421.5,8950.5 1499,9028 2728,9028 2918,8838 4477,8838 4600,8961 4600,9211.2 v2(4693,9304.2)
BLMH_SDI: R378.1 R407.2 U2.1 U5.1 U11.1 U14.1 | length 17251.4
  L1_Top Layer w11: v1(929.13,9001.58) 969.93,8960.79 U2.1@992.91,8960.79 ; v1(930.93,7579.46) 971.73,7538.66 U5.1@994.71,7538.66 ; v1(932.45,2655.22) 973.25,2614.42 U11.1@996.23,2614.42 ; v1(932.52,1235.89) 973.32,1195.09 U14.1@996.3,1195.09 ; v2(4671,9242) 4745.12,9242 R407.2@4745.32,9242.2
  L4_Signal Layer 1 w5.5: v1(932.52,1235.89) 980.14,1283.5 1106.29,1283.5 1197.86,1191.93 1443.19,1191.93 1677,1425.74 1677,2479.26 1645.79,2510.47 1151.21,2510.47 1121.74,2481 929.78,2481 903.52,2507.27 903.52,2626.29 v1(932.45,2655.22) 974.99,2697.77 1111.28,2697.77 1195.05,2614 1447.83,2614 1785.5,2951.67 1785.5,3323.76 1406,3703.26 1406,4809.26 1593,4996.26 1593,6395 1670.5,6472.5 1670.5,7154.4 1670.45,7154.46 1670.45,7196.91 1670.5,7196.96 1670.5,7414.01 1649.8,7434.71 1137.01,7434.71 1108.31,7406 927.5,7406 902,7431.5 902,7550.53 v1(930.93,7579.46) 973.47,7622 1109.76,7622 1196.26,7535.5 1443.76,7535.5 1654,7745.74 1654,7806.05 1671.5,7823.55 1671.5,8829.76 1651.76,8849.5 1125.5,8849.5 1106,8830 922,8830 902,8850 902,8974.45 v1(929.13,9001.58) 1005.22,8925.5 1444.22,8925.5 1522.22,9003.5 2701.5,9003.5 2913,8792 4492,8792 4671,8971 v2(4671,9242)
  L12_Bottom Layer w11: R378.1@4623.5,9244 4669,9244 v2(4671,9242)
BLMH_SDO: R376.1 R405.2 U2.4 U5.4 U11.4 U14.4 | length 16635.8
  L1_Top Layer w11: v1(925.19,8860.93) 965.99,8901.73 U2.4@988.97,8901.73 ; v1(926.99,7438.8) 967.79,7479.6 U5.4@990.77,7479.6 ; v1(928.51,2514.57) 969.31,2555.37 U11.4@992.29,2555.37 ; v1(928.59,1095.23) 969.39,1136.03 U14.4@992.37,1136.03 ; v2(4693,9180.2) R405.2@4745.32,9180.2
  L4_Signal Layer 1 w5.5: v1(925.19,8860.93) 976.26,8912 1466.26,8912 ; v1(928.51,2514.57) 928.51,2620.76 994.02,2686.27 1106.52,2686.27 1190.28,2602.5 1452.6,2602.5 1797,2946.9 1797,3328.53 1418,3707.53 1418,4800 1612,4994 1612,6397.74 1682,6467.74 1682,7159.17 1681.95,7159.22 1681.95,7192.15 1682,7192.2 1682,7418.77 1654.56,7446.21 1198.79,7446.21 1153,7492 1002,7492 948,7438 927.8,7438 v1(926.99,7438.8) 926.99,7544.99 992.5,7610.5 1105,7610.5 1191.5,7524 1448.53,7524 1665.5,7740.97 1665.5,7801.29 1683,7818.79 1683,8834.53 1656.53,8861 1517.53,8861 1466.26,8912.26 1546,8992 2695,8992 2912,8775 4499,8775 4693,8969 v2(4693,9180.2) ; v1(928.59,1095.23) 960,1126.65 960,1240 992,1272 1101.52,1272 1193.09,1180.43 1447.96,1180.43 1688.5,1420.97 1688.5,2484.03 1650.55,2521.97 1232.03,2521.97 1186,2568 1003.75,2568 949.52,2513.77 v1@929.32,2513.77
  L12_Bottom Layer w11: R376.1@4625.06,9180.1 4625.16,9180.2 v2(4693,9180.2)
BLMK_LMX_SCK: C426.2 R426.1 R445.2 U19.16 U21.16 U24.19 | length 11909.2
  L1_Top Layer w9: v1(2143.7,3743.46) 2143.7,3733.36 2169.71,3707.35 2169.71,3700.31 2202.05,3667.97 2222.59,3667.97 U21.16@2222.93,3667.97 ; U19.16@2329.03,6149.66 2349.91,6149.66 2382.25,6117.32 2382.25,6110.28 2408.26,6084.27 v1(2408.26,6074.17)
  L1_Top Layer w9.84: 4480.31,4745.35 4482.99,4748.04 U24.19@4482.99,4766.5
  L1_Top Layer w11: v1(4450.47,4719.94) 4454.89,4719.94 4480.31,4745.35 ; v2(4656,9889) 4800,10033 R445.2@4874.82,10033
  L10_Signal Layer 2 w6.5: v1(4450.47,4719.94) 4450.47,4741.47 4459,4750 4490,4750 4503,4737 4503,4569 4349,4415 4114,4415 4044,4345 3541.68,4345 2752.68,3556 2584.68,3556 2497.18,3468.5 2329.82,3468.5 2222,3576.32 2222,3735.32 2199.82,3757.5 2157.74,3757.5 v1(2143.7,3743.46) 2143.7,3727.7 2136.75,3720.75 2109.25,3720.75 2083,3747 2083,4363.32 2257,4537.32 2257,5280 2459.5,5482.5 2459.5,6022.93 v1(2408.26,6074.17) 2408.26,6173.26 3038.5,6803.5 3038.5,7523.5 3980,8465 3980,8911 3919,8972 3919,9434 3955,9470 3955,9909 4102,10056 4489,10056 v2(4656,9889)
  L12_Bottom Layer w11: v1(4450.47,4719.94) 4450.47,4694.52 4459.47,4685.52 C426.2@4458.97,4685.02 ; R426.1@4605.5,9886 4608.5,9889 v2(4656,9889)
BLMK_LMX_SDI: C425.2 R427.1 R447.2 U19.17 U21.17 U24.20 | length 11882.6
  L1_Top Layer w9: v1(2113.65,3740.78) 2153.71,3700.72 2153.71,3690.46 2195.54,3648.63 U21.17@2222.59,3648.63 ; U19.17@2329.38,6169 2356.42,6169 2398.25,6127.17 2398.25,6116.91 v1(2438.31,6076.84)
  L1_Top Layer w9.84: 4502.68,4740.15 U24.20@4502.68,4766.5
  L1_Top Layer w11: v1(4484,4721.47) 4502.68,4740.15 ; v2(4676,9818) 4680,9818 4831,9969 R447.2@4874.82,9969
  L10_Signal Layer 2 w6.5: v1(4484,4721.47) 4484,4576.2 4339.8,4432 4099,4432 4029,4362 3533,4362 2739.5,3568.5 2579.5,3568.5 2492,3481 2335,3481 2236,3580 2236,3745 2206,3775 2147.87,3775 v1(2113.65,3740.78) 2095.5,3758.94 2095.5,4358.14 2278,4540.64 2278,5279 2472,5473 2472,6043.16 v1(2438.31,6076.84) 2438.31,6185.63 3055,6802.32 3055,7516 3998,8459 3998,9251 3938,9311 3938,9429 3968,9459 3968,9882 4124.5,10038.5 4455.5,10038.5 v2(4676,9818)
  L12_Bottom Layer w11: v1(4484,4721.47) 4484,4708.73 4487.2,4705.53 4487.2,4705.28 C425.2@4507.97,4684.51 ; R427.1@4607.5,9699 4607.5,9749.5 v2(4676,9818)
BLMK_LMX_SDO: R428.1 R449.2 U75.1 | length 1175.4
  L1_Top Layer w11: U75.1@4206.99,9224.47 4256.47,9224.47 4277,9245 4277,9292 4310,9325 4515,9325 4759,9569 v2(4759,9654) ; v2(4830,9781) 4830,9780 R449.2@4874.82,9780
  L12_Bottom Layer w11: R428.1@4608.5,9634 4656,9681.5 4730.5,9681.5 ; v2(4759,9654) 4758,9654 4730.5,9681.5 ; v2(4830,9781) 4730.5,9681.5
BLMK_LMX_SDO1: R187.2 U75.7 | length 3526.1
  L1_Top Layer w8.6: R187.2@2435.81,6535.21 v2(2435.81,6580.72)
  L1_Top Layer w11: v2(3926,8877) 4042.09,8993.09 4042.09,9220.01 4066.24,9244.16 U75.7@4081.01,9244.16
  L10_Signal Layer 2 w6.5: v2(2435.81,6580.72) 2652.72,6580.72 2991,6919 2991,7547.68 3926,8482.68 v2(3926,8877)
BLMK_LMX_SDO2: R227.2 U75.6 | length 7334.7
  L1_Top Layer w8.6: v2(2115.8,3237.26) R227.2@2115.8,3282.76
  L1_Top Layer w11: v2(3896,8900) 3896,8947 4014,9065 4014,9218 4059.84,9263.84 U75.6@4081.01,9263.84
  L10_Signal Layer 2 w6.5: v2(2115.8,3237.26) 2002,3351.06 2002,4300 2241,4539 2241,5290 2109,5422 2109,6459 2281,6631 2678,6631 2974,6927 2974,7560 3896,8482 v2(3896,8900)
BLMK_SCS: C427.2 J40.1 R429.2 R451.2 U24.18 | length 6770.3
  L1_Top Layer w8: 4452.16,4743.19 4454.95,4743.19
  L1_Top Layer w9.84: 4454.95,4743.21 4463.31,4751.58 U24.18@4463.31,4766.5
  L1_Top Layer w11: J40.1@3679.92,9690 3726.92,9643 R429.2@3874.5,9643 3916.5,9601 3993,9601 4057,9537 v2(4119,9537) 4176,9480 4492,9480 4606,9594 4606,9687 4824,9905 R451.2@4874.82,9905 ; v1(4410.47,4723.94) 4409.47,4723.94 4428.72,4743.19 4452.16,4743.19
  L10_Signal Layer 2 w6.5: v2(4119,9537) 4146.5,9509.5 4146.5,7441.5 4037,7332 4037,6862.32 4546.47,6352.85 4546.47,5784.93 4480.47,5718.93 4480.47,5162.57 4410.47,5092.57 v1(4410.47,4723.94)
  L12_Bottom Layer w11: C427.2@4409.97,4684.58 4410.47,4685.08 v1(4410.47,4723.94)
BLMX1_SCS: J40.3 R410.2 R430.2 R452.2 U19.24 | length 5864.9
  L1_Top Layer w8: v1(2227.18,6286.92) 2244.39,6269.72 U19.24@2244.39,6253.99
  L1_Top Layer w11: J40.3@3679.92,9590 3726.92,9543 R430.2@3874.5,9543 3927.5,9490 4002,9490 4032,9460 4500.96,9460 4637,9596.04 4637,9678 4801,9842 R452.2@4874.82,9842 R452.2@4871.82,9839 ; v2(3982,9323) 3998.5,9323 R410.2@4023,9347.5
  L10_Signal Layer 2 w6.5: v1(2227.18,6286.92) 2287.26,6347 2562,6347 3026,6811 3026,7540 3967.5,8481.5 3967.5,8905.82 3906.5,8966.82 3906.5,8967.5 3904,8970 3904,9468 v2(3928,9492)
  L12_Bottom Layer w11: v2(3928,9492) 3928,9377 v2(3982,9323)
BLMX2_SCS: J40.5 R431.2 R454.2 U21.24 | length 8165
  L1_Top Layer w8: U21.24@2307.23,3563.98 2307.23,3548.26 v1@2324.44,3531.05
  L1_Top Layer w11: J40.5@3679.92,9490 3726.92,9443 R431.2@3874.5,9443 3912.75,9404.75 4007.75,9404.75 4038,9435 4500,9435 4782,9717 R454.2@4874.82,9717
  L10_Signal Layer 2 w6.5: v1(2327.63,3534.25) 3105.5,4312.12 3105.5,5168.5 2869,5405 2869,6563 3068,6762 3068,7500 4010.5,8442.5 4010.5,9397.5 v2(4004,9404)
BUF_CLKIN_SEL0: J23.2 U23.13 U58.6 | length 958.8
  L1_Top Layer w11: v2(3303,4845) 3312,4845 3330.13,4863.13 U23.13@3330.13,4881.29 ; J23.2@3610.74,4639.66 3563,4591.92 3563,4259 3595.46,4226.54 U58.6@3662.32,4226.54
  L12_Bottom Layer w11: v2(3303,4845) 3460,4688 3562.39,4688 J23.2@3610.74,4639.66
BUF_CLKIN_SEL1: J23.1 U23.16 U58.7 | length 864.1
  L1_Top Layer w11: U23.16@3389.19,4881.29 3389.19,4859.81 3401,4848 v2(3413,4848) ; J23.1@3610.74,4739.66 3663,4687.39 3663,4388 3612,4337 3612,4268 3627.87,4252.13 U58.7@3662.32,4252.13
  L12_Bottom Layer w11: v2(3413,4848) 3450,4811 3539.39,4811 J23.1@3610.74,4739.66
CALTRG1: J7.1 R66.2 U8.E7 | length 1447.6
  L1_Top Layer w3.5: U8.E7@2413.91,8272.34 2398.08,8288.17 2398.08,8412.16 2424.32,8438.4 2424.32,8662.36 2511.96,8750
  L1_Top Layer w11: 2511.96,8750 2647.64,8885.68 3131.69,8885.68 v1(3237.92,8991.91)
  L12_Bottom Layer w11: J7.1@3221.08,9074.99 3237.92,9058.15 v1(3237.92,8991.91)
CALTRG2: J18.1 R147.2 U17.E7 | length 1504.1
  L1_Top Layer w3.5: U17.E7@2417.24,1926.34 2401.41,1942.18 2401.41,2066.16 2385.17,2082.4 2385.17,2197 2423.76,2235.59 2423.76,2319.76 2487,2383
  L1_Top Layer w11: 2487,2383 2643.68,2539.68 3184.3,2539.68 v1(3291.01,2646.38)
  L12_Bottom Layer w11: v1(3291.01,2646.38) J18.1@3291.01,2725.21
CLK1+*: C91.2 R73.2 T1.1 | length 147.7
  L1_Top Layer w6: T1.1@1828.98,8283 1870.29,8283 R73.2@1906.17,8247.12 1908.29,8245 C91.2@1960.92,8245
CLK1-*: C97.2 R73.1 T1.3 | length 141.1
  L1_Top Layer w6: T1.3@1828.98,8183 1889.29,8183 R73.1@1906.17,8199.88 1911.29,8205 C97.2@1960.92,8205
CLK2+*: C251.2 R154.2 T2.1 | length 147.7
  L1_Top Layer w6: T2.1@1832.31,1937 1873.62,1937 1910.2,1900.42 1911.62,1899 C251.2@1964.25,1899
CLK2-*: C257.2 R154.1 T2.3 | length 141.1
  L1_Top Layer w6: T2.3@1832.31,1837 1892.62,1837 1908.79,1853.18 1914.62,1859 C257.2@1964.25,1859
CLK-IN: R296.1 R392.2 T3.6 | length 125.6
  L1_Top Layer w11: v2(5290.37,4440) R392.2@5338.81,4488.44
  L12_Bottom Layer w11: R296.1@5251.46,4399 5290.37,4437.91 v2(5290.37,4440)
CLK-IN*: R301.2 R308.2 R392.1 R401.1 | length 78.1
  L1_Top Layer w11: R392.1@5357.19,4506.81 R308.2@5385,4479 5412.13,4451.87 R301.2@5412.5,4451.87
CLK_1+: C90.1 C91.1 C92.1 U8.F1 | length 227
  L1_Top Layer w6: v1(2008.17,8245) 2029.91,8245 2044.32,8230.59 2200.81,8230.59 2211.06,8240.84 U8.F1@2224.94,8240.84
CLK_1-: C93.1 C97.1 C99.1 U8.G1 | length 227.1
  L1_Top Layer w6: v1(2008.17,8205) 2029.91,8205 2044.51,8219.59 2200.81,8219.59 2211.06,8209.35 U8.G1@2224.94,8209.35
CLK_2+: C250.1 C251.1 C252.1 U17.F1 | length 227
  L1_Top Layer w6: v1(2011.5,1899) 2033.25,1899 2047.65,1884.6 2204.15,1884.6 2214.39,1894.85 U17.F1@2228.27,1894.85
CLK_2-: C253.1 C257.1 C259.1 U17.G1 | length 227.1
  L1_Top Layer w6: v1(2011.5,1859) 2033.25,1859 2047.84,1873.6 2204.15,1873.6 2214.39,1863.35 U17.G1@2228.27,1863.35
CLKIN0_N: C400.2 U24.38 | length 176.8
  L1_Top Layer w6: U24.38@4764.49,4890.51 4782.3,4890.51 4786.64,4886.17 4908.06,4886.17 4922.66,4900.77 C400.2@4933.42,4900.77
CLKIN0_P: C397.2 U24.37 | length 174.2
  L1_Top Layer w6: U24.37@4764.49,4870.83 4782.3,4870.83 4786.64,4875.17 4909.96,4875.17 4918.36,4866.77 C397.2@4933.42,4866.77
CLKIN1_N: C404.2 C405.2 U24.35 | length 191.9
  L1_Top Layer w6: U24.35@4764.49,4831.46 4782.3,4831.46 4786.64,4827.11 4808.45,4827.11 4846.56,4789 4867.61,4789 4880.62,4802.01 C405.2@4894.89,4802.01 4931.99,4802.01 C404.2@4932.98,4801.02
CLKIN1_P: C351.2 C403.2 U24.34 | length 193.1
  L1_Top Layer w6: U24.34@4764.49,4811.77 4782.3,4811.77 4786.64,4816.11 4803.89,4816.11 4842,4778 4867.61,4778 4880.62,4764.99 C351.2@4894.89,4764.99 4928.95,4764.99 C403.2@4932.98,4769.02
CLKIN_SEL0: R371.1 R599.2 U24.58 | length 5844.5
  L1_Top Layer w9.84: U24.58@4561.73,5112.95 v1(4561.73,5147.2)
  L1_Top Layer w11: v2(5023.09,5284.94) 5024.55,5286.39 R371.1@5069.53,5286.39
  L10_Signal Layer 2 w6.5: v2(4124,9954) 4124,9585 4162,9547 4162,7435 4052,7325 4052,6869 4584.5,6336.5 4584.5,5769.18 4518.5,5703.18 4518.5,5155.5 4526.8,5147.2 v1(4561.73,5147.2)
  L12_Bottom Layer w11: v2(4124,9954) 4198.09,9954 R599.2@4199.5,9954 ; v1(4561.73,5147.2) 4717.53,5303 5005.03,5303 v2(5023.09,5284.94)
CLKIN_SEL1: R370.1 R602.1 U24.59 | length 5645.5
  L1_Top Layer w9.84: v1(4541.47,5172.94) 4542.05,5172.36 U24.59@4542.05,5112.95
  L1_Top Layer w11: v2(4153,9810) 4154,9809 R602.1@4199.01,9809 ; v2(5021.56,5350.94) 5023.01,5352.39 R370.1@5067.99,5352.39
  L10_Signal Layer 2 w6.5: v2(4153,9810) 4153,9590 4175,9568 4175,7420 4072,7317 4072,6871.36 4597,6346.36 4597,5764 4531,5698 4531,5183.41 v1(4541.47,5172.94)
  L12_Bottom Layer w11: v1(4541.47,5172.94) 4694.47,5325.94 4996.56,5325.94 v2(5021.56,5350.94)
CLKINN: R309.1 R311.2 T3.3 | length 625.6
  L1_Top Layer w6: R309.1@5160.46,4776.4 v2(5181.92,4797.86)
  L12_Bottom Layer w6: T3.3@5105.64,4398.11 5105.51,4398.11 R311.2@5058.81,4444.81 5048.72,4454.9 5048.72,4518 5023,4543.72 5023,4759 5054.5,4790.5 5094.06,4790.5 5124.28,4760.28 5144.34,4760.28 v2(5181.92,4797.86)
CLKINN0: J27.1 R290.1 R291.2 | length 829
  L1_Top Layer w6: R290.1@5024.4,4900.77 R291.2@5060.72,4900.77
  L1_Top Layer w10: R291.2@5060.97,4901.02 5063.98,4898.02 5660.08,4898.02 5704.79,4942.72 J27.1@5704.79,5071.8
CLKINN1: C400.1 R290.2 | length 39
  L1_Top Layer w6: C400.1@4959.4,4900.77 R290.2@4998.42,4900.77
CLKINN*: C404.1 R305.1 R309.2 R312.2 R395.1 | length 218.8
  L1_Top Layer w6: C404.1@4958.96,4801.02 4969.46,4790.52 4985.51,4790.52 R312.2@4996,4801.01 5006.51,4790.5 5024.51,4790.5 R305.1@5032,4797.99 5046.27,4797.99 5053.76,4790.5 5094.06,4790.5 5111.67,4772.89 ; 5113.78,4770.78 5111.67,4772.89 ; R395.1@5142.09,4758.03 5131.44,4768.67 5115.89,4768.67 5111.67,4772.89
CLKINP: R296.2 R297.2 R302.1 T3.1 | length 589.2
  L1_Top Layer w6: v2(5078.92,4694.86) R302.1@5100.38,4716.32
  L12_Bottom Layer w6: v2(5078.92,4694.86) 5116.5,4732.44 5116.5,4752.5 5089.5,4779.5 5059.06,4779.5 5034,4754.44 5034,4548.28 5057,4525.28 5120.1,4525.28 R297.2@5130.19,4515.19 5130.19,4514.99 T3.1@5176.35,4468.82
CLKINP0: J26.1 R278.1 R281.2 | length 829.4
  L1_Top Layer w6: R278.1@5024.4,4866.77 R281.2@5060.73,4866.77
  L1_Top Layer w10: R281.2@5060.73,4866.77 R281.2@5060.97,4867.01 5063.98,4870.02 5659.92,4870.02 5704.79,4825.15 J26.1@5704.79,4696.07
CLKINP1: C397.1 R278.2 | length 39
  L1_Top Layer w6: C397.1@4959.4,4866.77 R278.2@4998.42,4866.77
CLKINP*: C403.1 R298.1 R302.2 R305.2 R399.1 | length 206.7
  L1_Top Layer w6: C403.1@4958.96,4769.02 4969.46,4779.52 4985.48,4779.52 R298.1@4996,4768.99 5006.51,4779.5 5024.51,4779.5 R305.2@5032,4772.01 5046.27,4772.01 5053.76,4779.5 5089.5,4779.5 5108.11,4760.89 5108.11,4745.34 R302.2@5118.75,4734.69
CLKOUT_TYPE0: J23.4 U23.9 U58.4 | length 997.6
  L1_Top Layer w11: v2(3238,4849) 3251.39,4862.39 U23.9@3251.39,4881.29 ; v2(3604,4175) 3604.36,4175.36 U58.4@3662.32,4175.36
  L12_Bottom Layer w11: v2(3238,4849) 3238,4779 3326,4691 3377,4691 3480,4588 3542,4588 3563,4567 3563,4473.92 J23.4@3604,4432.92 ; v2(3604,4175) 3610.74,4181.74 J23.4@3610.74,4439.66
CLKOUT_TYPE1: J23.3 U23.32 U58.5 | length 1469.4
  L1_Top Layer w11: v2(3232,5146) 3232,5123 3251.39,5103.61 U23.32@3251.39,5070.26 ; U58.5@3662.32,4200.95 3663.37,4202 v2(3735,4202)
  L12_Bottom Layer w11: v2(3232,5146) 3433,5146 3508,5071 3508,4925 3662,4771 3662,4590.92 J23.3@3610.74,4539.66 3660.74,4489.66 3660.74,4276.26 v2(3735,4202)
CPOUT1: C398.2 C399.2 R359.2 U24.32 | length 2235.7
  L1_Top Layer w9.84: U24.32@4738.9,4766.5 4738.9,4749.51 4745,4743.41
  L1_Top Layer w11: 4745,4743.41 4780.97,4707.44 C399.2@4780.97,4705.64 C398.2@4828.97,4705.64 4867.61,4667 v1(4867.89,4667) ; v2(5353,6290) 5470.82,6290 R359.2@5526.87,6233.95
  L10_Signal Layer 2 w6.5: v1(4867.89,4667) 4925,4667 4968,4710 4968,4848 5093,4973 5093,6030 v2(5353,6290)
CPOUT2: C393.1 C395.1 U24.46 | length 149.5
  L1_Top Layer w9.84: U24.46@4764.49,5047.99 4800,5047.99
  L1_Top Layer w11: 4800,5047.99 4828.53,5047.99 4849.35,5068.82 C395.1@4849.35,5087.47 4885.94,5087.47 C393.1@4886.47,5086.95
DCLKOUT0+: C394.1 R274.2 U24.1 | length 515.3
  L1_Top Layer w6: C394.1@3941.09,5169.44 C394.1@3942.02,5170.37 ; R274.2@3993.95,5170.37 4011.76,5170.37 4035.14,5146.99 4164.9,5146.99 4228.87,5083.02 4395.88,5083.02 4400.22,5087.36 U24.1@4418.03,5087.36
  L1_Top Layer w10: C394.1@3942.02,5170.37 R274.2@3993.95,5170.37
DCLKOUT0-: C396.1 R273.2 U24.2 | length 515.7
  L1_Top Layer w6: C396.1@3941.09,5114.44 C396.1@3942.92,5112.61 ; R273.2@3993.95,5112.61 4011.76,5112.61 4035.14,5135.99 4160.34,5135.99 4224.31,5072.02 4395.88,5072.02 4400.22,5067.68 U24.2@4418.03,5067.68
  L1_Top Layer w10: C396.1@3942.92,5112.61 R273.2@3993.95,5112.61
DCLKOUT2+: C401.1 R289.2 U24.15 | length 350.8
  L1_Top Layer w6: C401.1@4131.63,4698.08 C401.1@4133.01,4699.46 ; R289.2@4184.01,4699.46 4201.82,4699.46 4222.7,4678.58 4235.89,4678.58 4364.74,4807.43 4395.88,4807.43 4400.22,4811.77 U24.15@4418.03,4811.77
  L1_Top Layer w10: C401.1@4133.01,4699.46 R289.2@4184.01,4699.46
DCLKOUT2-: C402.1 R288.2 U24.16 | length 350.8
  L1_Top Layer w6: C402.1@4131.63,4648.08 C402.1@4133.01,4646.7 ; R288.2@4184.01,4646.7 4201.82,4646.7 4222.7,4667.58 4240.45,4667.58 4369.3,4796.43 4395.88,4796.43 4400.22,4792.09 U24.16@4418.03,4792.09
  L1_Top Layer w10: C402.1@4133.01,4646.7 R288.2@4184.01,4646.7
DCLKOUT12+: C413.1 R365.2 U24.62 | length 722.2
  L1_Top Layer w6: R365.2@3994.28,5420.88 4012.09,5420.88 4035.47,5397.5 4061.39,5397.5 4145.89,5313 4378.45,5313 4478.65,5212.79 4478.65,5135.11 4482.99,5130.76 U24.62@4482.99,5112.95
  L1_Top Layer w10: C413.1@3944.28,5420.88 R365.2@3994.28,5420.88
DCLKOUT12-: C415.1 R364.2 U24.63 | length 722.2
  L1_Top Layer w6: R364.2@3994.28,5363.13 4012.09,5363.13 4035.47,5386.5 4056.83,5386.5 4066.33,5377 4066.33,5363.17 4079.08,5350.42 4092.92,5350.42 4101.36,5341.97 4101.36,5324.64 4107.08,5318.92 4124.42,5318.92 4141.33,5302 4373.89,5302 4467.65,5208.24 4467.65,5135.11 4463.31,5130.76 U24.63@4463.31,5112.95
  L1_Top Layer w10: C415.1@3944.28,5363.13 R364.2@3994.28,5363.13
DCLKOUT12_N: C415.2 J4.1 J46.Z21 | length 7334.6
  L1_Top Layer w10: J4.1@3433.66,5432.82 3433.66,5433.02 3433.66,5540.29 3502.19,5608.82 ; 3502,5609.02 3590.48,5609.02 3821.5,5378 3858.41,5378 3871.91,5364.5 v1(3895.66,5364.5)
  L4_Signal Layer 1 w4.9: v1(3895.66,5364.5) 3917.16,5386 3937.97,5386 3959,5407.03 3959,5762 4081,5884 4694,5884 4889,6079 4889,6307.64 4899.21,6317.85 4997.76,6317.85 5015,6335.09 5015,6367.51 4997.76,6384.75 4773.21,6384.75 4763,6394.96 4763,6417.44 4773.21,6427.65 4997.76,6427.65 5015,6444.89 5015,6477.31 4997.76,6494.55 4899.21,6494.55 4889,6504.76 4889,6586.44 4889,6609.84 4899.21,6620.05 5010.76,6620.05 5028,6637.29 5028,6669.71 5010.76,6686.95 4760.21,6686.95 4750,6697.16 4750,6719.64 4760.21,6729.85 5010.76,6729.85 5028,6747.09 5028,6779.51 5010.76,6796.75 4760.21,6796.75 4750,6806.96 4750,6829.44 4760.21,6839.65 5010.76,6839.65 5028,6856.89 5028,6889.31 5010.76,6906.55 4899.21,6906.55 4889,6916.76 4889,7004 5309,7424 6042,7424 6457.01,7839.01 6744.11,7839.01 v1(6763.11,7820.01)
DCLKOUT12_P: C413.2 J3.1 J46.Z20 | length 7334.6
  L1_Top Layer w10: J3.1@3433.66,5812.82 3433.66,5705.35 3502,5637.02 ; 3502.19,5636.82 3502,5637.02 ; v1(3895.66,5419.5) 3871.91,5419.5 3858.41,5406 3833.09,5406 3602.08,5637.02 3502,5637.02
  L4_Signal Layer 1 w4.9: v1(3895.66,5419.5) 3917.16,5398 3933,5398 3947,5412 3947,5766.97 4076.03,5896 4689.03,5896 4877,6083.97 4877,6312.61 4894.24,6329.85 4992.79,6329.85 5003,6340.06 5003,6362.54 4992.79,6372.75 4768.24,6372.75 4751,6389.99 4751,6422.41 4768.24,6439.65 4992.79,6439.65 5003,6449.86 5003,6472.34 4992.79,6482.55 4894.24,6482.55 4877,6499.79 4877,6586.44 4877,6614.81 4894.24,6632.05 5005.79,6632.05 5016,6642.26 5016,6664.74 5005.79,6674.95 4755.24,6674.95 4738,6692.19 4738,6724.61 4755.24,6741.85 5005.79,6741.85 5016,6752.06 5016,6774.54 5005.79,6784.75 4755.24,6784.75 4738,6801.99 4738,6834.41 4755.24,6851.65 5005.79,6851.65 5016,6861.86 5016,6884.34 5005.79,6894.55 4894.24,6894.55 4877,6911.79 4877,7008.97 5304.03,7436 6037.03,7436 6452.04,7851.01 6744.11,7851.01 v1(6763.11,7870.01)
DEVCLKIN1: J10.1 T1.6 | length 230.8
  L1_Top Layer w11: J10.1@1473.08,8282.9 1473.18,8283 T1.6@1703.79,8283
DEVCLKIN2: J21.1 T2.6 | length 230.6
  L1_Top Layer w11: J21.1@1476.51,1937 T2.6@1707.12,1937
